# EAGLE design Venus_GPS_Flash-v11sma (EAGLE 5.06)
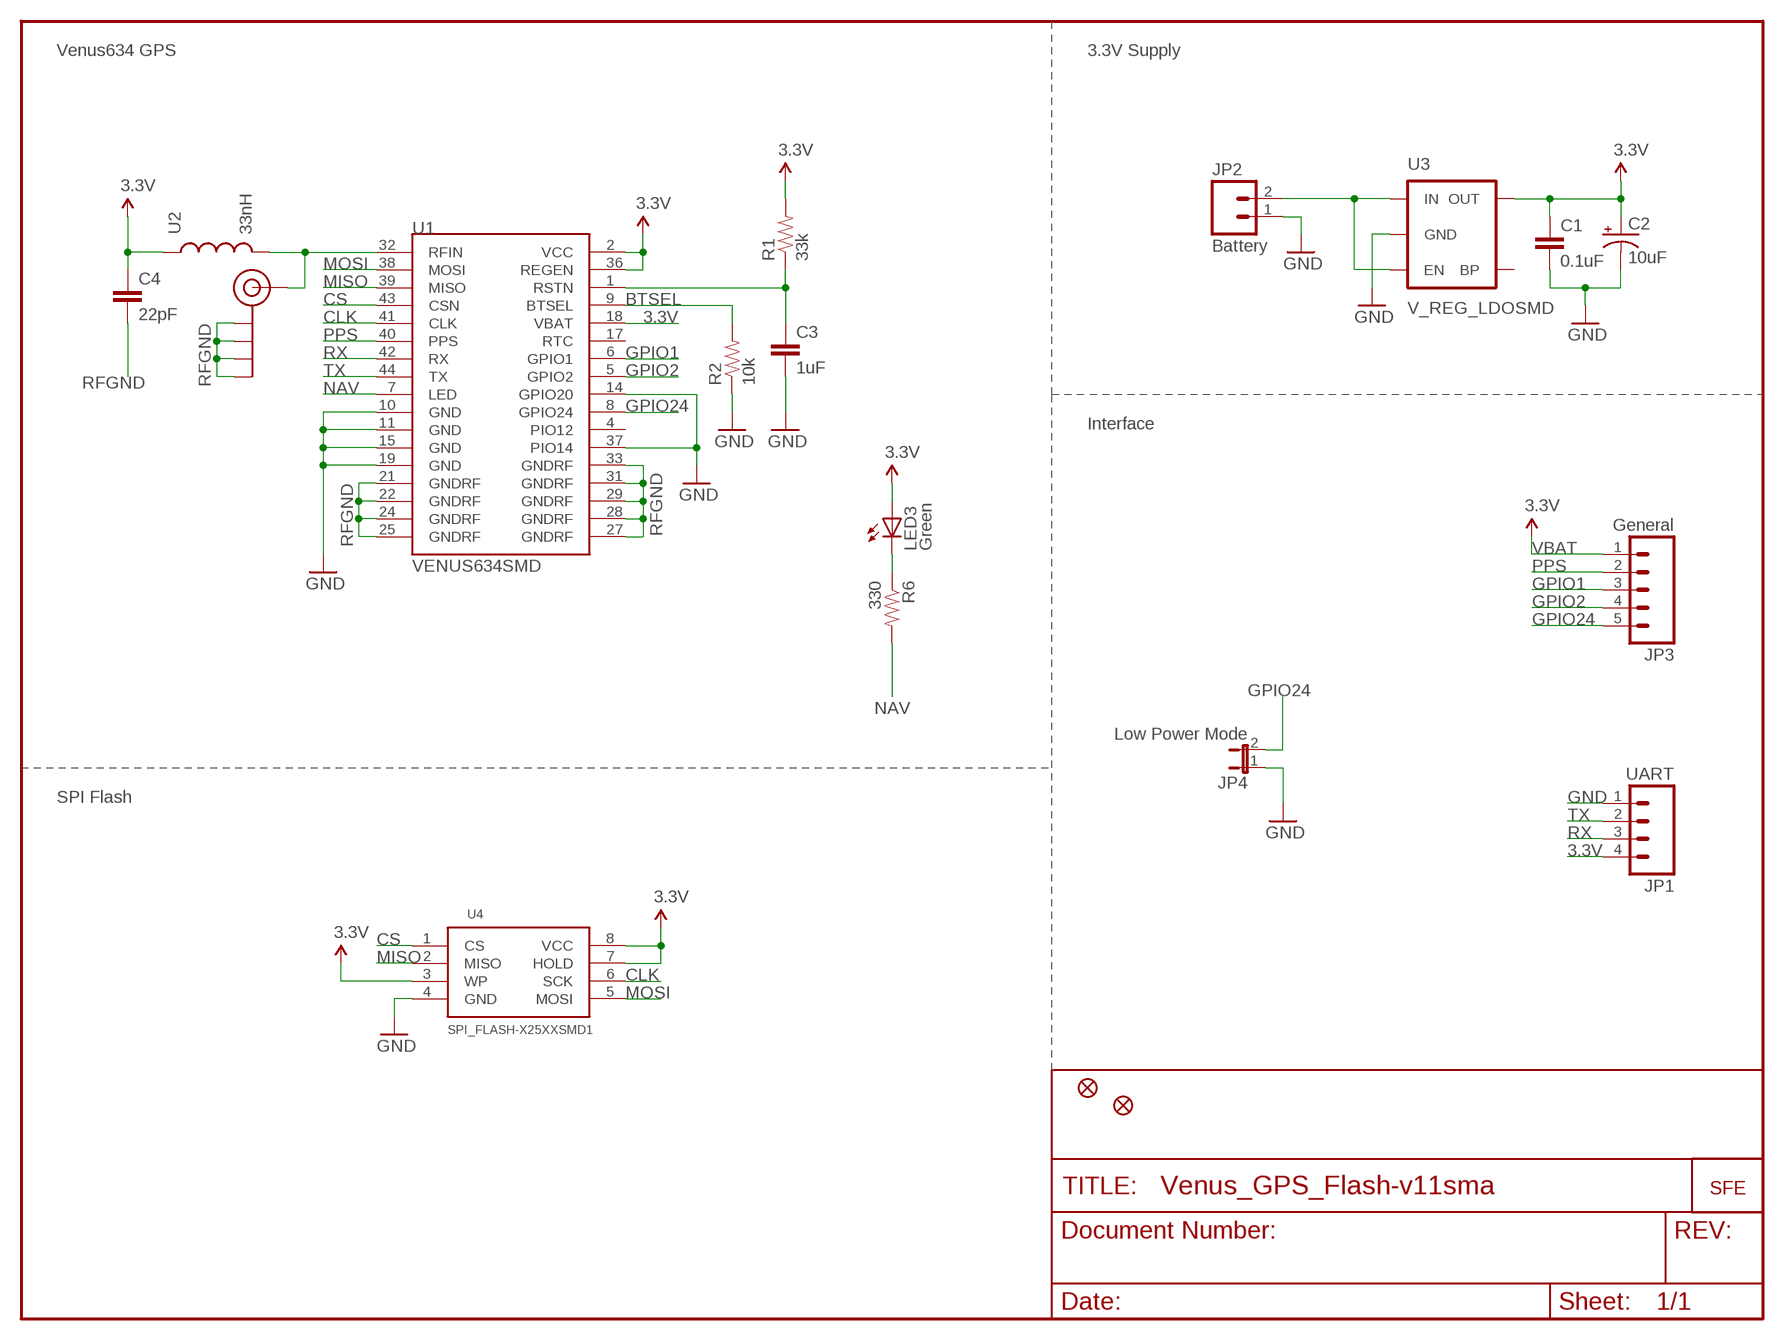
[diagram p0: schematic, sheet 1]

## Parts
C1  0.1uF  CAP0402  [C0402]
C2  10uF  CAP_POL1206  [EIA3216]
C3  1uF  CAP0402  [C0402]
C4  22pF  CAP0402  [C0402]
J$1  SMA_EDGE  [SMA-EDGE]
JP1  UART  M04PTH  [1X04]
JP2  Battery  M02-JST-2MM-SMT  [S2B-PH]
JP3  General  M05PTH  [1X05]
JP4  Low Power Mode  JUMPER-2SMD-NC  [SJ_2S]
JP5  FIDUCIAL1X2.5  [FIDUCIAL-1X2.5]
JP6  FIDUCIAL1X2.5  [FIDUCIAL-1X2.5]
LED3  Green  LED0603  [LED-0603]
R1  33k  RESISTOR0402  [C0402]
R2  10k  RESISTOR0402  [C0402]
R6  330  RESISTOR0402  [C0402]
U1  VENUS634SMD  [LGA44]
U2  33nH  INDUCTOR0402  [C0402]
U3  V_REG_LDOSMD  [SOT23-5]
U4  SPI_FLASH-X25XXSMD1  [SO08-EIAJ]
U$1  LOGO-SFESK  [SFE-LOGO-FLAME]

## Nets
3.3V: C1.1 C2.A(+) C4.1 JP1.4 JP3.1 LED3.A R1.2 U1.2(VCC) U1.18(VBAT) U1.36(REGEN) U2.1 U3.5(OUT) U4.3(WP) U4.7(HOLD) U4.8(VCC)
BTSEL: R2.2 U1.9(BTSEL)
CLK: U1.41(CLK) U4.6(SCK)
CS: U1.43(CSN) U4.1(CS)
GND: C1.2 C2.C(-) C3.2 JP1.1 JP2.1 JP4.1 R2.1 U1.10(GND) U1.11(GND) U1.14(GPIO20) U1.15(GND) U1.19(GND) U1.37(PIO14) U3.2(GND) U4.4(GND)
GPIO1: JP3.3 U1.6(GPIO1)
GPIO2: JP3.4 U1.5(GPIO2)
GPIO24: JP3.5 JP4.2 U1.8(GPIO24)
MISO: U1.39(MISO) U4.2(MISO)
MOSI: U1.38(MOSI) U4.5(MOSI)
N$1: LED3.C R6.1
N$3: C3.1 R1.1 U1.1(RSTN)
N$14: J$1.SIG(SIGNAL) U1.32(RFIN) U2.2
NAV: R6.2 U1.7(LED)
PPS: JP3.2 U1.40(PPS)
RFGND: C4.2 J$1.GND@0(GND) J$1.GND@1(GND) J$1.GND@2(GND) J$1.GND@3(GND) U1.21(GNDRF) U1.22(GNDRF) U1.24(GNDRF) U1.25(GNDRF) U1.27(GNDRF) U1.28(GNDRF) U1.29(GNDRF) U1.31(GNDRF) U1.33(GNDRF)
RX: JP1.3 U1.42(RX)
TX: JP1.2 U1.44(TX)
VBATT: JP2.2 U3.1(IN) U3.3(EN)
Unconnected: U1.4(PIO12) U1.17(RTC) U3.4(BP)

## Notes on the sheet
- Venus634 GPS | 3.3V Supply
- Interface
- VBAT
- SPI Flash

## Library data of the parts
C1 C3 C4 = SparkFun:CAP: Capacitor
C2 = SparkFun:CAP_POL: Capacitor Polarized
J$1 = SparkFun:SMA_EDGE: SMA Antenna Connector End launch SMA connector. The paste layer has been removed so that the connector can be hand soldered onto the board after reflow.
JP1 = SparkFun:M04: Header 4 Standard 4-pin 0.1" header. Use with straight break away headers (SKU : PRT-00116), right angle break away headers (PRT-00553), swiss pins (PRT-00743), machine pins (PRT-00117), and female headers (PRT-00115). Molex polarized connector foot print use with SKU : PRT-08231 with associated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
JP2 = SparkFun:M02: Header 2
JP3 = SparkFun:M05: Header 5 Standard 5-pin 0.1" header. Use with straight break away headers (SKU : PRT-00116), right angle break away headers (PRT-00553), swiss pins (PRT-00743), machine pins (PRT-00117), and female headers (PRT-00115). Molex polarized connector foot print use with SKU : PRT-08230 with associated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
JP4 = SparkFun:JUMPER-2: Jumper
JP5 JP6 = abes:FIDUCIAL: Fiducial Alignment Points
LED3 = SparkFun:LED: LEDs
R1 R2 R6 = SparkFun:RESISTOR: Resistor
U1 = SparkFun:VENUS634: Venus634 from SkyTraq
U2 = SparkFun:INDUCTOR: Inductors
U3 = SparkFun:V_REG_LDO: Voltage Regulator LDO Standard 150mA LDO voltage regulator in SOT-23 layout. Micrel part MIC5205. BP (by-pass) pin is used to lower output noise with 470pF cap.
U4 = SparkFun:SPI_FLASH-X25XX: 8pin SPI Flash series x25xx. Works with devices like W25X32 and BR25L32
U$1 = SparkFun:LOGO-SFE: Spark Fun Electronics PCB Logo

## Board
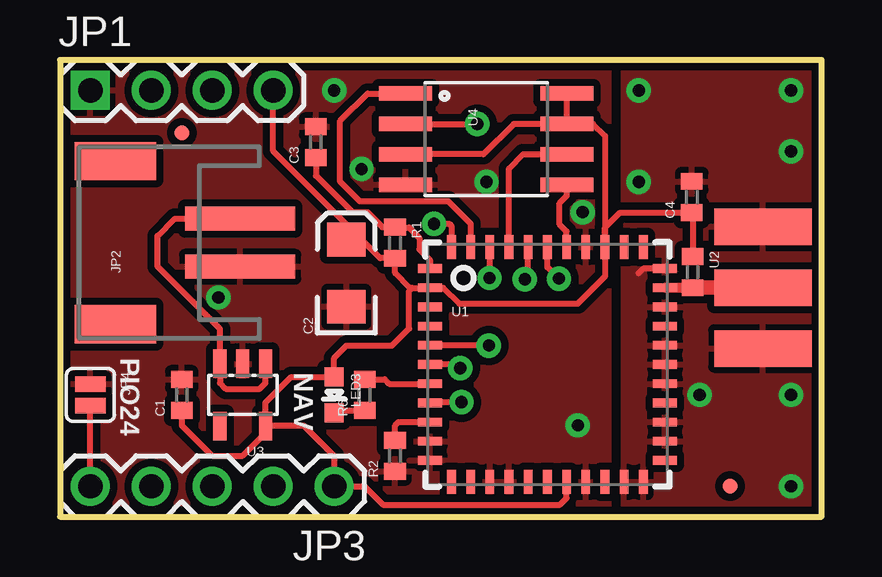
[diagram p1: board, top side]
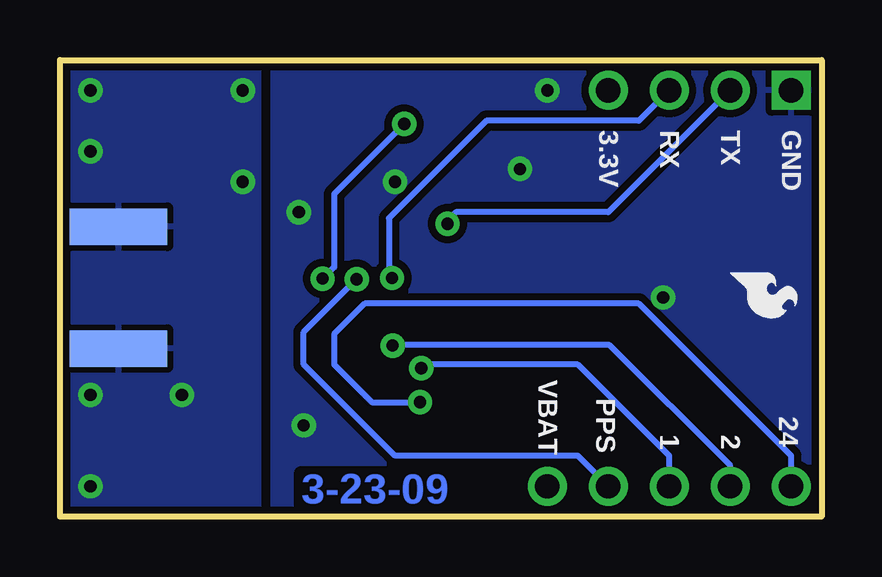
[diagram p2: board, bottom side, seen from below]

Size 31.75 x 19.05 mm. Coordinates in mm from the lower left corner, seen from the top.
Outline: 0,0 31.75,0 31.75,19.05 0,19.05 0,0
Copper layers (1*16): Top 0.0356mm / dielectric 1.5011mm / Bottom 0.0356mm
Design rules "default": minimum track width 8mil, minimum drill 20mil, track to track 8mil, track to pad 8mil, pad to pad 8mil, via to via 8mil, smd to smd 8mil, copper to edge 10mil, drill to drill 8mil, minimum pad ring 12mil, minimum via ring 10mil, stop-mask expansion 4mil, vias tented up to drill 20mil, thermal gap 10mil

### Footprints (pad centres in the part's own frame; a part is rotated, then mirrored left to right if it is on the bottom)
C0402 = smd 0.7 x 0.9: 1 -0.65,0; 2 0.65,0
EIA3216 = smd 1.4 x 1.6: A 1.4,0; C -1.4,0
SMA-EDGE = smd 1.524 x 4.064: GND@0 0,0; GND@1 5.08,0; SIG 2.54,0 | smd 1.524 x 4.064 bottom: GND@2 0,0; GND@3 5.08,0
1X04 = drill 1.016 square: 1 0,0 | drill 1.016 round: 2 2.54,0; 3 5.08,0; 4 7.62,0
S2B-PH = smd 1 x 4.6: 1 -1,-3.7; 2 1,-3.7 | smd 1.6 x 3.4: NC1 -3.4,1.5; NC2 3.4,1.5
1X05 = drill 1.016 round: 1 0,0; 2 2.54,0; 3 5.08,0; 4 7.62,0; 5 10.16,0
SJ_2S = smd 0.635 x 1.27: 1 -0.45,0; 2 0.45,0
FIDUCIAL-1X2.5 = smd 0.635 x 0.635: 1 0,0
LED-0603 = smd 0.8 x 0.8: A 0,-0.75; C 0,0.75
LGA44 = smd 1 x 0.36: 1 -4.9,4; 2 -4.9,3.2; 3 -4.9,2.4; 4 -4.9,1.6; 5 -4.9,0.8; 6 -4.9,0; 7 -4.9,-0.8; 8 -4.9,-1.6; 9 -4.9,-2.4; 10 -4.9,-3.2; 11 -4.9,-4; 23 4.9,-4; 24 4.9,-3.2; 25 4.9,-2.4; 26 4.9,-1.6; 27 4.9,-0.8; 28 4.9,0; 29 4.9,0.8; 30 4.9,1.6; 31 4.9,2.4; 32 4.9,3.2; 33 4.9,4 | smd 0.36 x 1: 12 -4,-4.9; 13 -3.2,-4.9; 14 -2.4,-4.9; 15 -1.6,-4.9; 16 -0.8,-4.9; 17 0,-4.9; 18 0.8,-4.9; 19 1.6,-4.9; 20 2.4,-4.9; 21 3.2,-4.9; 22 4,-4.9; 34 4,4.9; 35 3.2,4.9; 36 2.4,4.9; 37 1.6,4.9; 38 0.8,4.9; 39 0,4.9; 40 -0.8,4.9; 41 -1.6,4.9; 42 -2.4,4.9; 43 -3.2,4.9; 44 -4,4.9
SOT23-5 = smd 0.55 x 1.2: 1 -0.95,-1.3; 2 0,-1.3; 3 0.95,-1.3; 4 0.95,1.3; 5 -0.95,1.3
SO08-EIAJ = smd 0.61 x 2.21: 1 -1.905,-3.378; 2 -0.635,-3.378; 3 0.635,-3.378; 4 1.905,-3.378; 5 1.905,3.353; 6 0.635,3.353; 7 -0.635,3.353; 8 -1.905,3.353

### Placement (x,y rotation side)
C1  5.08,5.08 90 top
C2  11.94,10.16 90 top
C3  10.67,15.62 90 top
C4  26.34,13.34 90 top
J$1  29.31,7.01 90 top
JP1  1.27,17.78 0 top
JP2  3.81,11.43 90 top
JP3  11.43,1.27 180 top
JP4  1.27,5.08 270 top
JP5  27.94,1.27 0 top
JP6  5.08,16 0 top
LED3  11.43,5.08 180 top
R1  13.97,11.43 270 top
R2  13.97,2.54 90 top
R6  12.7,5.08 90 top
U1  20.32,6.35 0 top
U2  26.38,10.2 270 top
U3  7.62,5.08 180 top
U4  17.78,15.75 270 top
U$1  3.81,10.16 270 bottom

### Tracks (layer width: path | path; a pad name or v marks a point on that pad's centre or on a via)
3.3V
  Top 0.254: 22.72,11.81 U1.36 22.73,11.24 22.73,10.03 21.59,8.89 16.64,8.89 15.98,9.55 U1.2 14.68,9.55 | 22.72,11.81 22.72,12.05 | 22.72,12.05 23.35,12.69 C4.1 26.38,12.65 U2.1 | 22.72,12.05 22.73,12.06 | 14.68,9.55 14.58,9.55 13.97,10.16 R1.2 13.35,10.78 12.7,11.43 12.07,11.43 C2.A 11.94,12.19 8.89,15.24 JP1.4 | 22.72,11.81 22.73,11.82 22.73,15.88 22.23,16.38 U4.7 | U4.3 17.65,15.11 18.92,16.38 U4.7 | U4.7 U4.8 | 14.68,9.55 14.55,9.42 14.55,7.85 13.84,7.14 11.94,7.14 11.43,6.63 LED3.A 9.64,5.83 8.57,4.76 U3.5 | C1.1 5.08,3.81 6.35,2.54 7.62,2.54 8.57,3.49 U3.5 | U1.18 21.12,0.78 20.85,0.51 13.46,0.51 12.7,1.27 JP3.1 11.43,2.54 10.16,3.81 8.6,3.81 U3.5
BTSEL
  Top 0.254: U1.9 14.11,3.95 13.97,3.81 R2.2
CLK
  Top 0.254: U1.41 18.72,14.53 19.3,15.11 U4.6
CS
  Top 0.254: U1.43 17.12,12.22 16.18,13.16 12.5,13.16 11.68,13.97 11.68,16.51 12.83,17.65 U4.1
GND  (via drill 0.51)
  other vias: 17.78,13.97 21.79,12.7 11.43,17.78 21.59,3.81 12.57,14.5 6.6,9.14
  pour Bottom (isolate 0.305): 0,19.05 22.86,19.05 22.86,0 0,0
  pour Top (isolate 0.305): 0,19.05 22.86,19.05 22.86,0 0,0
GPIO1  (via drill 0.51)
  Top 0.254: U1.6 16.66,6.35 v16.69,6.2
  Bottom 0.254: JP3.3 6.35,2.54 10.16,6.35 16.66,6.35 v16.69,6.2
GPIO2  (via drill 0.51)
  Top 0.254: U1.5 v17.87,7.15 v17.88,7.14
  Bottom 0.254: JP3.4 3.81,2.13 8.84,7.16 17.86,7.16 v17.88,7.14 17.86,7.11
GPIO24  (via drill 0.51)
  Top 0.254: v16.74,4.78 15.45,4.78 U1.8 | JP3.5 JP4.2
  Bottom 0.254: v16.74,4.78 18.75,4.78 20.32,6.35 20.32,7.62 19.05,8.89 7.62,8.89 1.27,2.54 JP3.5
MISO  (via drill 0.51)
  Top 0.254: U4.2 v17.4,16.38 | U1.39 20.32,10.41 v20.8,9.93
  Bottom 0.254: v17.4,16.38 20.32,13.46 20.32,10.41 v20.8,9.93
MOSI
  Top 0.254: U1.38 21.12,11.9 20.83,12.19 20.83,13.08 21.13,13.39 U4.5
N$1
  Top 0.254: R6.1 11.53,4.43 LED3.C
N$3
  Top 0.254: U1.1 15.42,10.72 14.99,11.15 14.99,11.63 14.55,12.06 13.98,12.06 R1.1 13.45,12.08 12.83,12.7 12.19,12.7 10.67,14.22 C3.1
N$14
  Top 0.254: U2.2 | U1.32
  Top 0.406: U1.32 U2.2
  Top 0.61: U2.2 J$1.SIG
NAV
  Top 0.254: U1.7 13.73,5.55 13.55,5.73 R6.2
PPS  (via drill 0.51)
  Top 0.254: U1.40 19.52,10.05 v19.38,9.91
  Bottom 0.254: JP3.2 10.16,2.54 17.78,2.54 21.59,6.35 21.59,7.7 v19.38,9.91
RFGND  (via drill 0.51)
  Top 0.254: U1.33 24.32,10.35 24.13,10.16
  other vias: 24.13,17.78 30.48,15.24 30.48,1.27 30.48,17.78 24.13,13.97 26.67,5.08 30.48,5.08
  pour Top (isolate 0.305): 23.5,19.05 23.5,0 31.75,0 31.75,19.05
  pour Bottom (isolate 0.305): 23.5,19.05 23.5,0 31.75,0 31.75,19.05
RX  (via drill 0.51)
  Top 0.254: U1.42 17.92,10.1 v17.91,9.96
  Bottom 0.254: JP1.3 7.62,16.51 13.97,16.51 18.03,12.45 18.03,9.98 v17.91,9.96
TX  (via drill 0.51)
  Top 0.254: U1.44 16.32,12.13 16.23,12.22 v15.6,12.22
  Bottom 0.254: JP1.2 8.89,12.7 15.24,12.7 15.6,12.34 v15.6,12.22
VBATT
  Top 0.254: U3.1 8.57,5.57 8.33,5.33 6.91,5.33 6.67,5.57 U3.3 6.67,7.83 4.06,10.44 4.06,11.71 4.79,12.43 JP2.2

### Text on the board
Bottom: 3-23-09
tPlace: PIO24 | NAV
bPlace: GND | TX | RX | 3.3V | VBAT | PPS | 24 | 2 | 1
